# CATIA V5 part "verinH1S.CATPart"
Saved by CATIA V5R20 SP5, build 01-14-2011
Part number: verinH1S
Publications: "Droite.2", "Point.3", "Point.1"
Bounding box of the stored display mesh (mm): x 0 to 0, y -70 to 55, z 240 to 1175
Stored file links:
  U:\think motion\fin\verinH1S.CATPart
  U:\think motion\fin\squelette.CATProduct
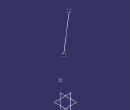
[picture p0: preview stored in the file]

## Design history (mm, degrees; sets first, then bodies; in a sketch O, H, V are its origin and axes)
Set1
  Point1: linked copy from another document
  Point2: linked copy from another document
Set2
  Line1: type PtPt, FirstPoint Point1, SecondPoint Point2
  Point3: type OnCurve, Support Line1, Length 600
  Line2: type PtPt, FirstPoint Point1, SecondPoint Point3
Body1 (main body)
